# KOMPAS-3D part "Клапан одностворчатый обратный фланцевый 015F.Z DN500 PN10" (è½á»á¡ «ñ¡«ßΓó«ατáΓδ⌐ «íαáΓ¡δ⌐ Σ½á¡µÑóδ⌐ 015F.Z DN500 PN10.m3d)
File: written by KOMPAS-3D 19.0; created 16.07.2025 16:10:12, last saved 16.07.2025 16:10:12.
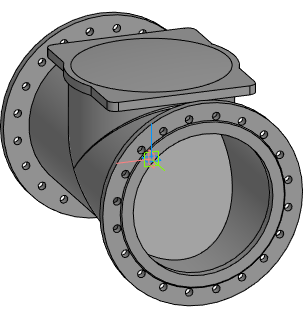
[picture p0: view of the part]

Document properties: Полное имя файла: E:\Dendor Работа Сачек\3D для проектировщиков\5.4 Тип 015F.Z. Клапан одностворчатый обратный фланцевый\stp_Клапан одностворчатый обратный фланцевый 015F.Z PN10_16\Клапан одностворчатый обратный фланцевый 015F.Z DN500 PN10.m3d

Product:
- Part/product: Клапан одностворчатый обратный фланцевый 015F.Z DN500 PN10

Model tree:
1. Операция без истории:1  (labels: Клапан одностворчатый обратный фланцевый 015F.Z DN500 PN10)
2. Операция без истории:2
